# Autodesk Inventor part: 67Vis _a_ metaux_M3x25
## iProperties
Created: 2011-01
Part Number: 67Vis _a_ metaux_M3x25
Document SubType Name: Modeling
Designer: eric
Density: 1 g/cm^3
Mass: 0.220255 g
Surface Area: 3.25153 cm^2
Volume: 0.220255 cm^3
Author: eric
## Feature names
1. Base1
